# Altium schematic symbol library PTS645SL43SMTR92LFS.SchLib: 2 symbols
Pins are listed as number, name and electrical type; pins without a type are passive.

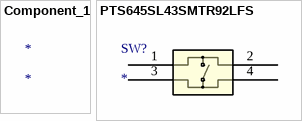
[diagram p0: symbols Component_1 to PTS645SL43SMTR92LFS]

## Component_1
designator *

## PTS645SL43SMTR92LFS
designator SW?
No Description Available; Mfr_Name: C&K Components
footprint PTS645SL43SMTR92LFS_CNK
pins: 1, 2, 3, 4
